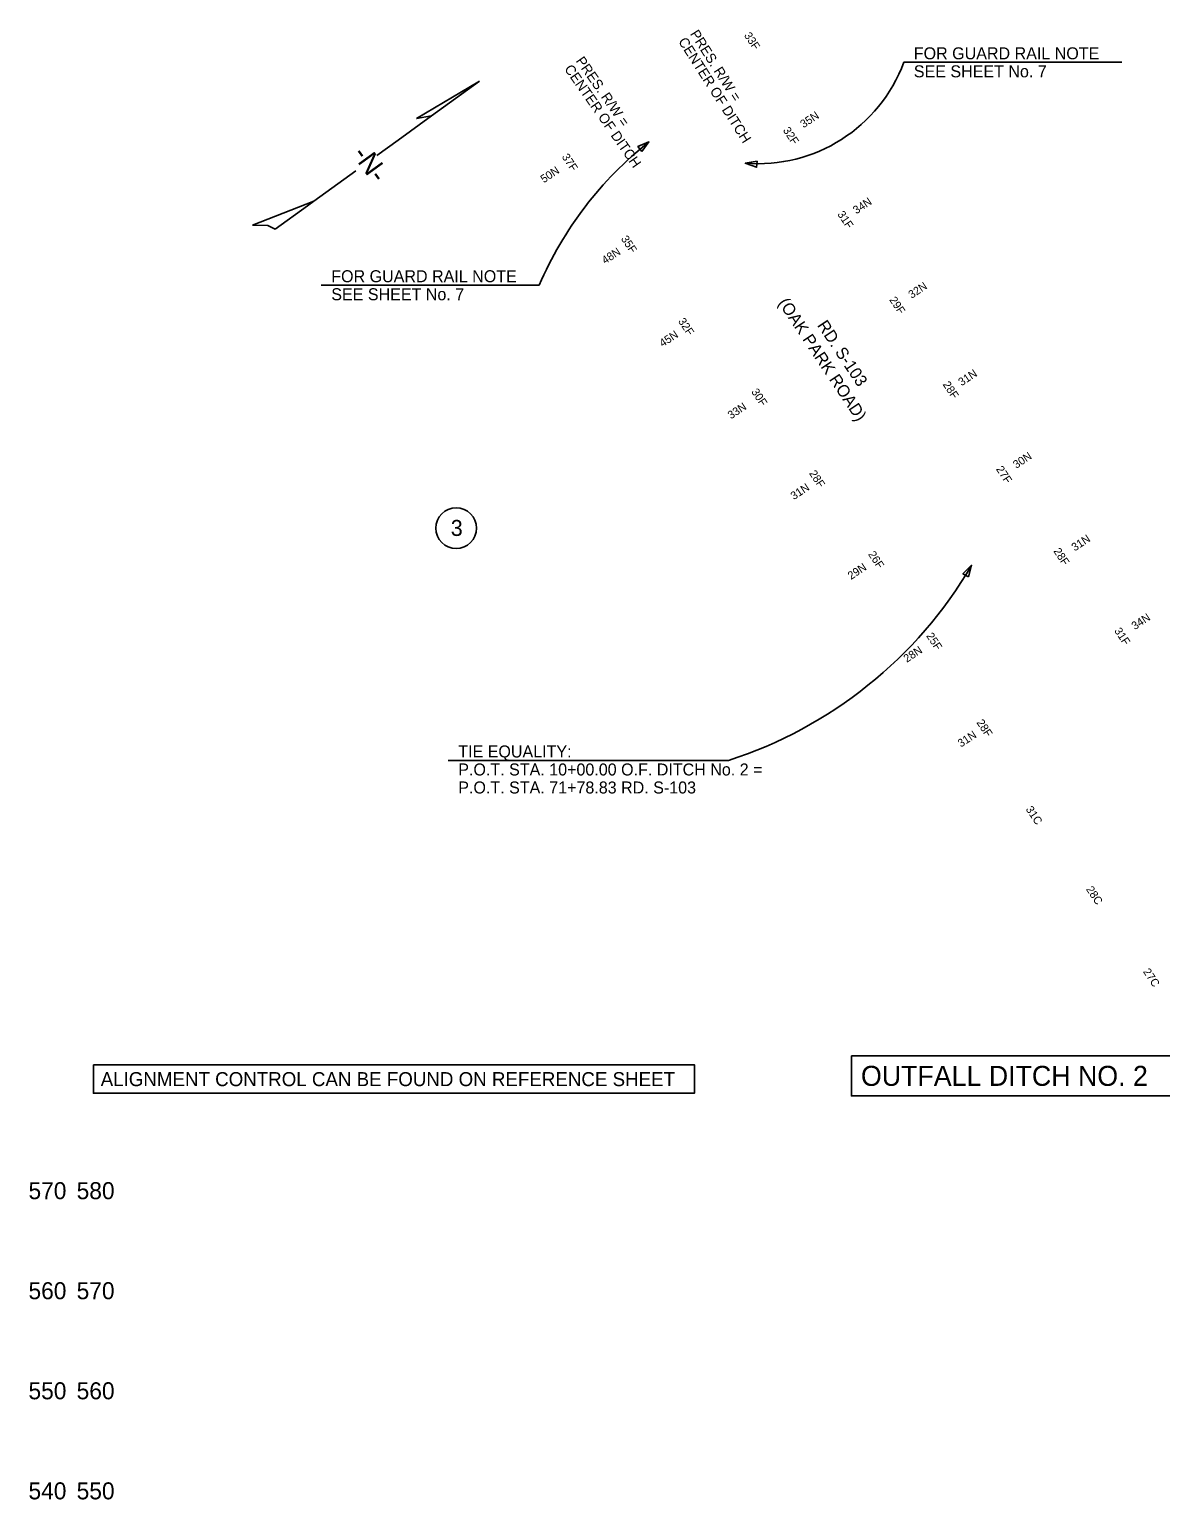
# Model space of a CAD drawing. Extents: x 1964849 to 1967422, y 1116563 to 1122211.
# Drawn here: x 1966573 to 1967138, y 1121475 to 1122210 of the extents above; entities that cross this region are included whole.
import ezdxf

# ---------------------------------------------------------------- set-up
doc = ezdxf.new("R2010")
doc.units = 0
for name, color, linetype in [('RD_DDB_Profile_Elev', 7, 'Continuous'), ('RD_EX_DV_TX_Prop', 7, 'Continuous'), ('RD_EX_Misc', 7, 'Continuous'), ('RD_EX_RW_TX', 7, 'Continuous'), ('RD_HC_Data', 7, 'Continuous'), ('RD_PD_TX_CstnLmt', 7, 'Continuous'), ('RD_Sketch1', 7, 'Continuous'), ('RD_TX_Drainage', 7, 'Continuous'), ('RD_TX_Misc1', 7, 'Continuous'), ('RD_TX_Misc2', 7, 'Continuous'), ('RD_TX_RoadID', 7, 'Continuous')]:
    doc.layers.add(name, color=color, linetype=linetype)

msp = doc.modelspace()

# ---------------------------------------------------------------- linework, layer by layer
at = {"layer": 'RD_EX_DV_TX_Prop'}
msp.add_circle((1966785.94, 1121960.93), 10.18, dxfattribs=at)
at = {"layer": 'RD_EX_Misc'}
for p, q in [((1966766.12, 1122165.66), (1966797.54, 1122184.31)), ((1966797.54, 1122184.31), (1966773.54, 1122166.92)), ((1966773.54, 1122166.92), (1966756.91, 1122154.87)), ((1966773.54, 1122166.92), (1966766.12, 1122165.66)), ((1966756.91, 1122154.87), (1966746.3, 1122147.18)), ((1966735.71, 1122139.51), (1966714.73, 1122124.32)), ((1966684.19, 1122112.37), (1966714.73, 1122124.32)), ((1966711.56, 1122122.01), (1966695.48, 1122110.37)), ((1966714.73, 1122124.32), (1966711.56, 1122122.01))]:
    msp.add_line(p, q, dxfattribs=at)
msp.add_lwpolyline([(1966695.48, 1122110.37), (1966691.84, 1122112.1), (1966684.19, 1122112.37)], dxfattribs=at)
at = {"layer": 'RD_HC_Data'}
msp.add_line((1966922.03, 1121844.81), (1966781.97, 1121844.81), dxfattribs=at)
msp.add_lwpolyline([(1967041.94, 1121936.54), (1967043.53, 1121942.33), (1967039.26, 1121938.11)], close=True, dxfattribs=at)
msp.add_arc((1966854.98, 1122052.8), 218.53, 287.86761, 329.63283, dxfattribs=at)
at = {"layer": 'RD_Sketch1'}
msp.add_lwpolyline([(1966604.58, 1121692.78), (1966905, 1121692.78), (1966905, 1121678.52), (1966604.58, 1121678.52)], close=True, dxfattribs=at)
at = {"layer": 'RD_TX_Misc1'}
for p, q in [((1967118.61, 1122193.69), (1967009.68, 1122193.69)), ((1966827.42, 1122082.3), (1966718.49, 1122082.3))]:
    msp.add_line(p, q, dxfattribs=at)
for points in [[(1966878.67, 1122149.12), (1966882.25, 1122153.94), (1966876.74, 1122151.56)], [(1966936.31, 1122144.34), (1966930.41, 1122143.27), (1966936.06, 1122141.25)]]:
    msp.add_lwpolyline(points, close=True, dxfattribs=at)
for centre, radius, start, end in [((1966936.78, 1122220.78), 77.77, 265.30495, 339.61537), ((1966996.8, 1122009.48), 184.37, 128.41144, 156.73401)]:
    msp.add_arc(centre, radius, start, end, dxfattribs=at)
at = {"layer": 'RD_TX_Misc2'}
msp.add_lwpolyline([(1966983.48, 1121697.21), (1967147.94, 1121697.21), (1967147.94, 1121677.21), (1966983.48, 1121677.21)], close=True, dxfattribs=at)

# ---------------------------------------------------------------- texts
at = {"layer": 'RD_DDB_Profile_Elev'}
for s, p in [('570', (1966572.14, 1121625.58)), ('580', (1966596.21, 1121625.58)), ('560', (1966572.14, 1121575.58)), ('570', (1966596.21, 1121575.58)), ('550', (1966572.14, 1121525.58)), ('560', (1966596.21, 1121525.58)), ('540', (1966572.14, 1121475.58)), ('550', (1966596.21, 1121475.58))]:
    msp.add_text(s, height=8.5, dxfattribs=at).set_placement(p)
at = {"layer": 'RD_EX_DV_TX_Prop'}
msp.add_text('3', height=8, dxfattribs=at).set_placement((1966783.23, 1121957.01))
at = {"layer": 'RD_EX_Misc'}
msp.add_text('-N-', height=10, rotation=305.92276, dxfattribs=at).set_placement((1966733.68, 1122147.66))
at = {"layer": 'RD_EX_RW_TX'}
for s, rotation, p in [('PRES. R/W = ', 302.50459, (1966902.64, 1122207.92)), ('CENTER OF DITCH', 302.50459, (1966896.74, 1122204.16)), ('PRES. R/W = ', 304.92557, (1966845.5, 1122194.39)), ('CENTER OF DITCH', 304.92557, (1966839.76, 1122190.39))]:
    msp.add_text(s, height=5, rotation=rotation, dxfattribs=at).set_placement(p)
at = {"layer": 'RD_HC_Data'}
for s, p in [('TIE EQUALITY:', (1966786.97, 1121846.31)), ('P.O.T. STA. 10+00.00 O.F. DITCH No. 2 =', (1966786.97, 1121837.31)), ('P.O.T. STA. 71+78.83 RD. S-103', (1966786.97, 1121828.31))]:
    msp.add_text(s, height=6, dxfattribs=at).set_placement(p)
at = {"layer": 'RD_PD_TX_CstnLmt'}
for s, p in [('33F', (1966929.66, 1122207.14)), ('32F', (1966949.07, 1122159.73)), ('37F', (1966838.55, 1122146.48)), ('31F', (1966976.31, 1122117.8)), ('35F', (1966868.12, 1122105.52)), ('29F', (1967002.26, 1122075)), ('32F', (1966896.69, 1122064.33)), ('28F', (1967028.99, 1122032.73)), ('30F', (1966933.28, 1122029.09)), ('28F', (1966962.19, 1121988.27)), ('27F', (1967055.61, 1121990.39)), ('28F', (1967084.3, 1121949.42)), ('26F', (1966991.7, 1121947.85)), ('25F', (1967020.7, 1121907.09)), ('31F', (1967114.71, 1121909.6)), ('28F', (1967045.86, 1121863.77)), ('31C', (1967070.46, 1121820.42)), ('28C', (1967100.63, 1121780.44)), ('27C', (1967129.09, 1121739.32))]:
    msp.add_text(s, height=4, rotation=303.6494, dxfattribs=at).set_placement(p)
at = {"layer": 'RD_Sketch1'}
msp.add_text('ALIGNMENT CONTROL CAN BE FOUND ON REFERENCE SHEET', height=7, dxfattribs=at).set_placement((1966608.23, 1121682.07))
at = {"layer": 'RD_TX_Drainage'}
for s, p in [('35N', (1966959.57, 1122160.69)), ('50N', (1966829.74, 1122133.24)), ('34N', (1966985.93, 1122117.68)), ('48N', (1966860.36, 1122092.63)), ('32N', (1967013.61, 1122075.46)), ('45N', (1966889.16, 1122051.22)), ('31N', (1967038.58, 1122031.78)), ('33N', (1966923.29, 1122015.21)), ('30N', (1967065.92, 1121990.5)), ('31N', (1966954.75, 1121974.86)), ('31N', (1967095.14, 1121949.22)), ('29N', (1966983.3, 1121934.98)), ('34N', (1967125.17, 1121909.9)), ('28N', (1967011.2, 1121893.56)), ('31N', (1967038.27, 1121851.23))]:
    msp.add_text(s, height=4, rotation=33.6494, dxfattribs=at).set_placement(p)
at = {"layer": 'RD_TX_Misc1'}
for s, p in [('FOR GUARD RAIL NOTE', (1967014.68, 1122195.19)), ('SEE SHEET No. 7', (1967014.68, 1122186.19)), ('FOR GUARD RAIL NOTE', (1966723.49, 1122083.8)), ('SEE SHEET No. 7', (1966723.49, 1122074.8))]:
    msp.add_text(s, height=6, dxfattribs=at).set_placement(p)
at = {"layer": 'RD_TX_Misc2'}
msp.add_text('OUTFALL DITCH NO. 2', height=10, dxfattribs=at).set_placement((1966988.27, 1121682.21))
at = {"layer": 'RD_TX_RoadID'}
for s, p in [('(OAK PARK ROAD)', (1966946.68, 1122073.51)), ('RD. S-103 ', (1966966.16, 1122062.28))]:
    msp.add_text(s, height=6, rotation=303.64939, dxfattribs=at).set_placement(p)

doc.saveas('drawing.dxf')
